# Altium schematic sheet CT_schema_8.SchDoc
size 386 x 278 mm
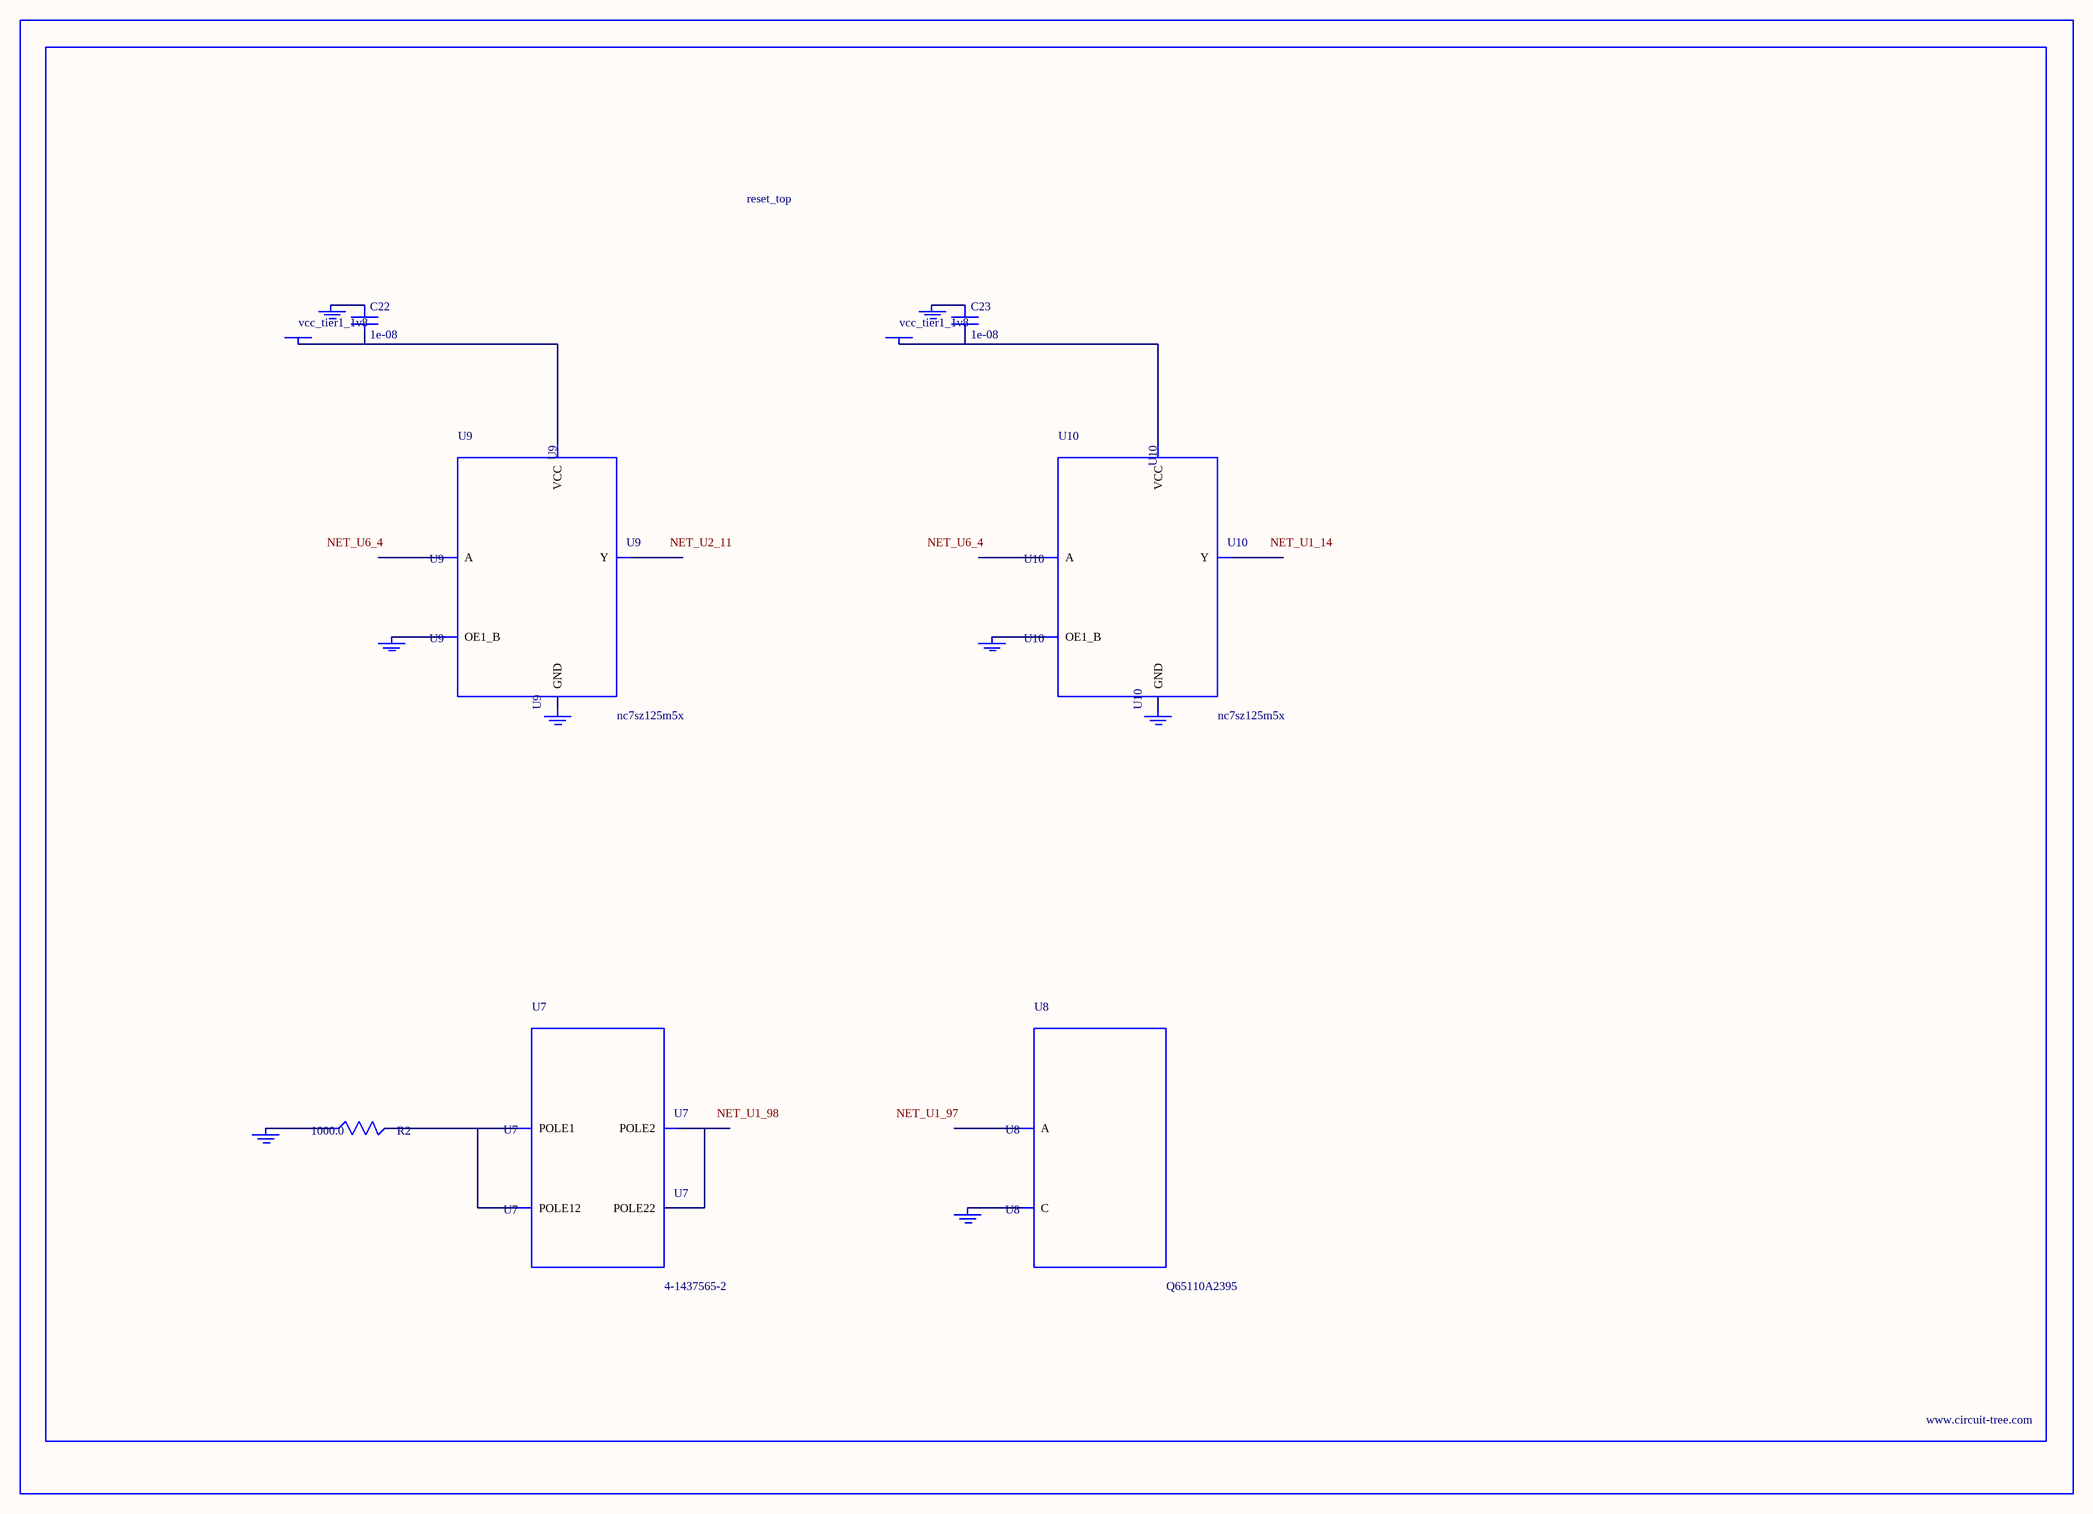
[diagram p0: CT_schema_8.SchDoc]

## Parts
BORDER7  (no value)
C22  1e-08  [C0402]
C23  1e-08  [C0402]
GND_INSTANCE_7_0  (no value)
GND_INSTANCE_7_1  (no value)
GND_INSTANCE_7_2  (no value)
GND_INSTANCE_7_3  (no value)
GND_INSTANCE_7_4  (no value)
GND_INSTANCE_7_5  (no value)
GND_INSTANCE_7_6  (no value)
GND_INSTANCE_7_7  (no value)
POWER_INSTANCE_7_0  vcc_tier1_1v8
POWER_INSTANCE_7_1  vcc_tier1_1v8
R2  1000.0  [R0603]
U7  4-1437565-2  [SW_4-1437565-2]
U8  Q65110A2395  [LGM67K-G1J2-24-Z]
U9  nc7sz125m5x  [NC7SZ125M5X]
U10  nc7sz125m5x  [NC7SZ125M5X]

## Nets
NetC22_1: C22.1 GND_INSTANCE_7_2.0(GND)
NetC22_2: C22.2 POWER_INSTANCE_7_0.0(PWR) U9.5(VCC)
NetC23_1: C23.1 GND_INSTANCE_7_5.0(GND)
NetC23_2: C23.2 POWER_INSTANCE_7_1.0(PWR) U10.5(VCC)
NetGND_INSTANCE_7_0_0: GND_INSTANCE_7_0.0(GND) R2.1
NetGND_INSTANCE_7_1_0: GND_INSTANCE_7_1.0(GND) U8.C
NetGND_INSTANCE_7_3_0: GND_INSTANCE_7_3.0(GND) U9.1(OE1_B)
NetGND_INSTANCE_7_4_0: GND_INSTANCE_7_4.0(GND) U9.3(GND)
NetGND_INSTANCE_7_6_0: GND_INSTANCE_7_6.0(GND) U10.1(OE1_B)
NetGND_INSTANCE_7_7_0: GND_INSTANCE_7_7.0(GND) U10.3(GND)
NetR2_2: R2.2 U7.1(POLE1) U7.2(POLE12)
NetU7_3: U7.3(POLE2) U7.4(POLE22)

Not connected (* = marked no-connect by the designer): U8 A; U9 2(A) 4(Y); U10 2(A) 4(Y)

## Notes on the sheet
- Labels drawn without touching a wire or pin: NET_U1_14, NET_U1_97, NET_U1_98, NET_U2_11, NET_U6_4

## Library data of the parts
BORDER7 = BORDER_PAGE7
C22 C23 = C0402C103K3RAC
GND_INSTANCE_7_0-GND_INSTANCE_7_7 = GND
POWER_INSTANCE_7_0 POWER_INSTANCE_7_1 = PWR
R2 = RC0603JR-071KL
